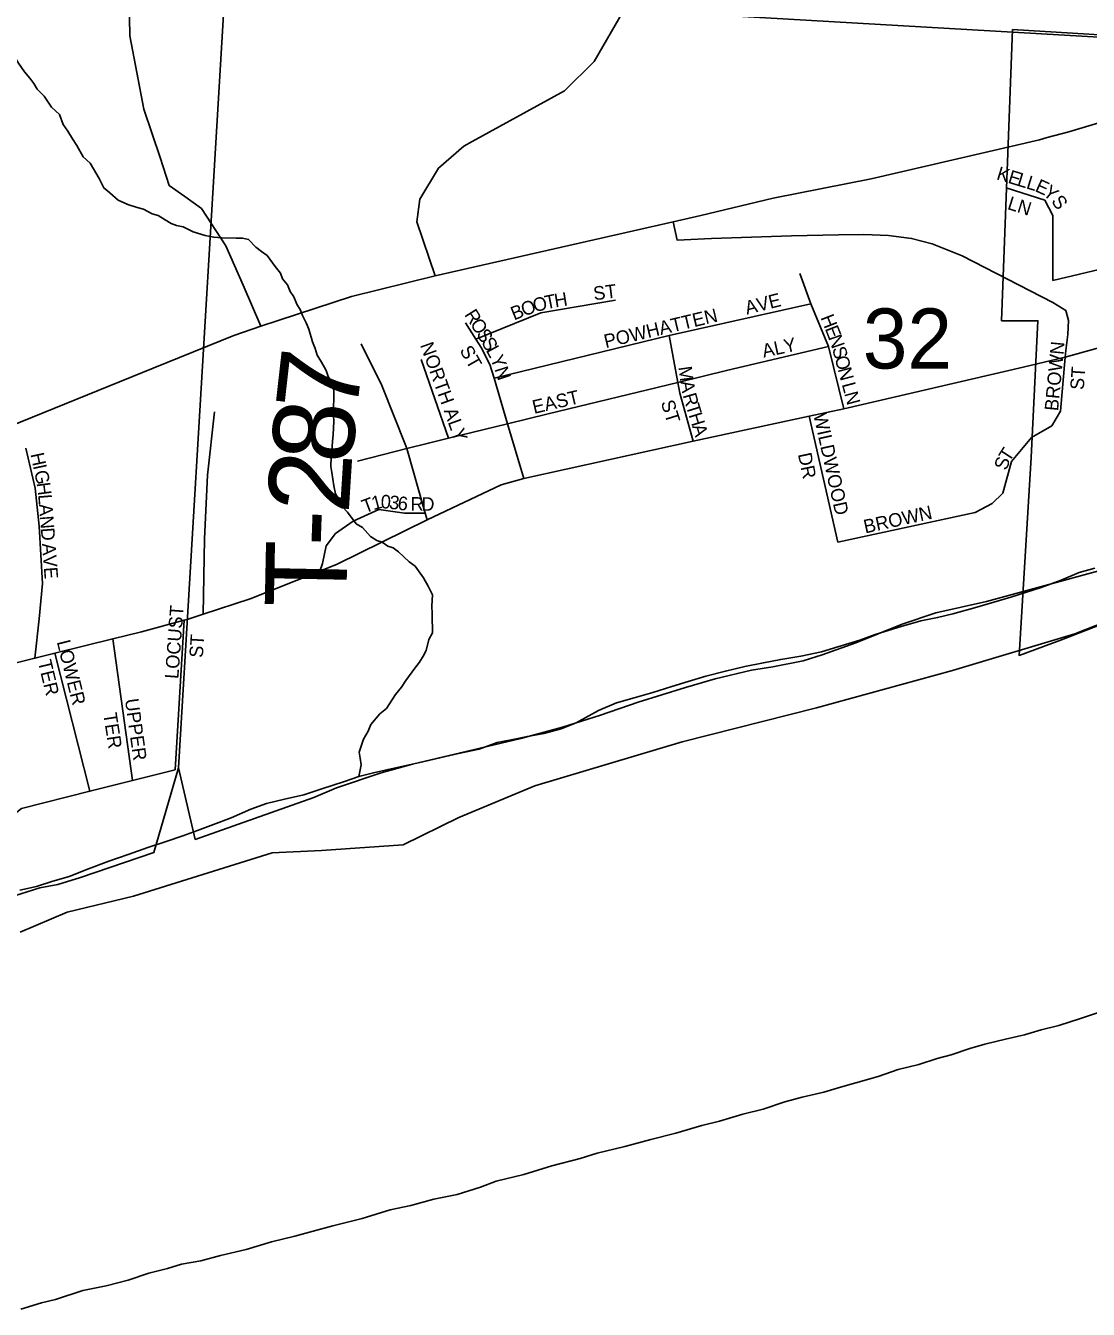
# Model space of a CAD drawing. Extents: x 0 to 34, y 0 to 22.
# Drawn here: x 3.368 to 4.109, y 15.164 to 16.058 of the extents above; entities that cross this region are included whole.
import ezdxf

# ---------------------------------------------------------------- set-up
doc = ezdxf.new("R2010")
doc.units = 0
for name, color, linetype in [('GM_X_City_Street', 7, 'Continuous'), ('GM_X_City_Street_Text', 7, 'Continuous'), ('GM_X_Corporation', 7, 'Continuous'), ('GM_X_County', 7, 'Continuous'), ('GM_X_County_Road', 7, 'Continuous'), ('GM_X_Interchange_Ramps', 7, 'Continuous'), ('GM_X_Major_River', 7, 'Continuous'), ('GM_X_Minor_River', 7, 'Continuous'), ('GM_X_Section', 7, 'Continuous'), ('GM_X_Section_Text', 7, 'Continuous'), ('GM_X_State_Route', 7, 'Continuous'), ('GM_X_Township', 7, 'Continuous'), ('GM_X_Township_Road', 7, 'Continuous'), ('GM_X_Township_Road_Text', 7, 'Continuous'), ('GM_X_Township_ROW', 7, 'Continuous'), ('GM_X_Township_Subdivision', 7, 'Continuous'), ('GM_X_Township_Subdivision_Text', 7, 'Continuous')]:
    doc.layers.add(name, color=color, linetype=linetype)

msp = doc.modelspace()

# ---------------------------------------------------------------- linework, layer by layer
at = {"layer": 'GM_X_City_Street'}
for points in [[(4.08456, 15.88074), (4.08464, 15.92599), (4.07896, 15.93664), (4.05197, 15.94531)], [(4.08456, 15.88074), (4.19618, 15.90713), (4.22201, 15.92)], [(4.09304, 15.82718), (4.1424, 15.84105), (4.16933, 15.84846), (4.26803, 15.87561), (4.3744, 15.90487), (4.44235, 15.92357)], [(4.06976, 15.77117), (4.08375, 15.77949), (4.08983, 15.78952), (4.09304, 15.82718)], [(4.0833, 15.82492), (4.09304, 15.82718)]]:
    msp.add_lwpolyline(points, dxfattribs=at)
at = {"layer": 'GM_X_Corporation'}
msp.add_lwpolyline([(4.14073, 15.64967), (4.09056, 15.63014), (4.06097, 15.61941), (4.06937, 15.75741), (4.07411, 15.85262), (4.04883, 15.85269), (4.05648, 16.05554), (4.29607, 16.04108)], dxfattribs=at)
at = {"layer": 'GM_X_County'}
msp.add_lwpolyline([(3.36466, 15.42637), (3.39726, 15.44049), (3.44353, 15.45159), (3.54023, 15.48177), (3.57475, 15.48336), (3.63165, 15.48727), (3.67032, 15.50633), (3.72339, 15.52846), (3.82616, 15.55905), (3.91983, 15.58279), (4.01463, 15.60881), (4.09995, 15.63443), (4.17199, 15.66269)], dxfattribs=at)
at = {"layer": 'GM_X_County_Road'}
for points in [[(3.65396, 15.88386), (3.64105, 15.9215), (3.64332, 15.93732), (3.65619, 15.959), (3.6738, 15.97433), (3.67979, 15.97757), (3.74411, 16.01283), (3.76477, 16.03339), (3.78552, 16.06911), (3.78668, 16.07724), (3.78765, 16.09175), (3.78406, 16.12231), (3.76062, 16.19637), (3.75023, 16.22244)], [(3.30564, 15.60024), (3.37488, 15.61744), (3.38872, 15.62088), (3.42928, 15.63096), (3.44921, 15.63591), (3.47881, 15.64392), (3.48179, 15.64473), (3.49225, 15.64816), (3.52496, 15.65889), (3.57339, 15.67813), (3.58555, 15.68296), (3.64839, 15.71388), (3.69988, 15.73832), (3.71568, 15.7427), (3.8337, 15.76866), (3.9146, 15.78602), (3.93887, 15.79127), (4.06381, 15.82038)], [(4.06381, 15.82038), (4.0833, 15.82492)]]:
    msp.add_lwpolyline(points, dxfattribs=at)
at = {"layer": 'GM_X_Interchange_Ramps'}
msp.add_lwpolyline([(3.8199, 15.92148), (3.82257, 15.90884), (3.84662, 15.90999), (3.90233, 15.91185), (3.93522, 15.91249), (3.95279, 15.91282), (3.96998, 15.912), (3.98609, 15.91003), (4.00039, 15.90624), (4.02127, 15.89786), (4.08457, 15.86531), (4.09365, 15.85971), (4.09542, 15.85281), (4.09509, 15.84295), (4.09361, 15.83193), (4.09304, 15.82718)], dxfattribs=at)
at = {"layer": 'GM_X_Major_River'}
for points in [[(4.11385, 15.68021), (4.10288, 15.67714), (4.09041, 15.67179), (4.07642, 15.66681), (4.06621, 15.66337), (4.05524, 15.65992), (4.04352, 15.65647), (4.0299, 15.65263), (4.01477, 15.64841), (4.00418, 15.64572), (3.99245, 15.64341), (3.97884, 15.63957), (3.96068, 15.63383), (3.9501, 15.63), (3.93459, 15.6254), (3.92325, 15.62195), (3.90887, 15.61887), (3.89487, 15.61655), (3.88276, 15.61424), (3.8699, 15.61154), (3.85629, 15.60847), (3.84267, 15.60501), (3.83019, 15.60118), (3.81884, 15.59773), (3.80561, 15.59352), (3.79275, 15.58968), (3.78027, 15.58623), (3.76779, 15.58088), (3.7523, 15.57248), (3.74171, 15.56828), (3.72961, 15.56483), (3.71826, 15.5629), (3.70691, 15.56059), (3.69707, 15.55866), (3.6846, 15.55407), (3.67022, 15.55099), (3.65812, 15.5483), (3.64525, 15.54523), (3.63164, 15.54215), (3.62104, 15.53984), (3.61083, 15.53754), (3.60062, 15.53485), (3.59079, 15.53141), (3.5749, 15.52643)], [(3.5749, 15.52643), (3.56243, 15.52222), (3.54881, 15.51914), (3.53633, 15.51607), (3.52536, 15.51224), (3.51175, 15.50613), (3.49927, 15.50154), (3.48831, 15.49734), (3.4781, 15.49351), (3.46637, 15.48969), (3.45352, 15.48547), (3.4399, 15.4805), (3.42629, 15.47591), (3.4123, 15.47056), (3.39869, 15.46521), (3.38659, 15.46176), (3.376, 15.45831), (3.36427, 15.45562)], [(3.36507, 15.16355), (3.37944, 15.16814), (3.38928, 15.17045), (3.40818, 15.17657), (3.42445, 15.18002), (3.43996, 15.18386), (3.45433, 15.18884), (3.46719, 15.19191), (3.47702, 15.19497), (3.49064, 15.19728), (3.50426, 15.20111), (3.52204, 15.20534), (3.53981, 15.2107), (3.55608, 15.21454), (3.56894, 15.21799), (3.58255, 15.22182), (3.60298, 15.22681), (3.62264, 15.23294), (3.63702, 15.23601), (3.6529, 15.24023), (3.66917, 15.24369), (3.68543, 15.24867), (3.6964, 15.25287), (3.71569, 15.25748), (3.73536, 15.26361), (3.75502, 15.2686), (3.76675, 15.27243), (3.78604, 15.27704), (3.80419, 15.28202), (3.82159, 15.28624), (3.83975, 15.29161), (3.85223, 15.29468), (3.86849, 15.29966), (3.88249, 15.30311), (3.89761, 15.30809), (3.90972, 15.31154), (3.92485, 15.315), (3.93657, 15.31845), (3.94716, 15.32152), (3.96267, 15.32573), (3.97666, 15.33071), (3.99104, 15.33417), (4.00389, 15.33838), (4.01373, 15.34106), (4.02658, 15.34527), (4.03718, 15.34834), (4.05155, 15.3518), (4.06479, 15.35487), (4.07651, 15.35832), (4.08861, 15.36139), (4.10374, 15.36637), (4.11774, 15.37097)]]:
    msp.add_lwpolyline(points, dxfattribs=at)
at = {"layer": 'GM_X_Minor_River'}
for points in [[(3.37418, 16.01798), (3.37122, 16.02183), (3.3675, 16.02608), (3.36345, 16.03223), (3.36013, 16.03761), (3.35569, 16.04377), (3.35197, 16.04764), (3.35551, 16.05519)], [(3.60062, 15.53485), (3.60223, 15.54308), (3.60155, 15.54766), (3.60087, 15.55185), (3.60406, 15.56091), (3.60719, 15.56656), (3.60916, 15.57109), (3.61535, 15.57859), (3.61996, 15.58231), (3.62619, 15.59209), (3.63045, 15.59734), (3.63356, 15.60185), (3.63977, 15.61049), (3.64288, 15.61461), (3.6456, 15.61875), (3.64757, 15.6229), (3.64959, 15.63047), (3.65194, 15.63499), (3.65201, 15.63879), (3.65172, 15.64373), (3.6518, 15.64867), (3.65151, 15.65362), (3.65203, 15.6616), (3.64911, 15.66773), (3.6458, 15.67348), (3.63988, 15.68157), (3.63577, 15.68468), (3.62832, 15.69164), (3.62458, 15.69437), (3.62081, 15.69557), (3.61707, 15.69829), (3.6133, 15.6995), (3.60881, 15.70223), (3.60323, 15.70841), (3.59874, 15.71115), (3.59282, 15.71923), (3.5891, 15.72309), (3.58728, 15.7273), (3.58433, 15.73192), (3.58329, 15.73764), (3.58193, 15.74678), (3.58125, 15.75098), (3.58137, 15.75782), (3.58183, 15.76199), (3.58231, 15.76845), (3.58278, 15.77338), (3.58332, 15.7825), (3.58301, 15.78669), (3.58332, 15.80417), (3.58189, 15.80913), (3.57932, 15.81374), (3.57788, 15.81795), (3.57457, 15.82371), (3.57163, 15.8287), (3.57019, 15.83328), (3.56838, 15.83788), (3.56588, 15.84667), (3.56407, 15.85126), (3.5615, 15.85624), (3.56005, 15.86007), (3.55748, 15.8643), (3.55529, 15.86928), (3.55271, 15.87312), (3.55089, 15.87772), (3.54756, 15.88196), (3.54611, 15.88578), (3.5424, 15.89041), (3.53686, 15.89811), (3.53274, 15.90084), (3.529, 15.90394), (3.5238, 15.90935), (3.51964, 15.91018), (3.5151, 15.91026), (3.50525, 15.91042), (3.49958, 15.9109), (3.49354, 15.91214), (3.48525, 15.91456), (3.47812, 15.91811), (3.47359, 15.91895), (3.46983, 15.92053), (3.4657, 15.92288), (3.46083, 15.926), (3.45669, 15.92721), (3.45068, 15.93036), (3.44616, 15.93157), (3.43975, 15.93358), (3.43299, 15.93674), (3.42702, 15.94178), (3.42291, 15.94527), (3.41962, 15.9518), (3.41337, 15.96255), (3.40852, 15.96681), (3.40411, 15.97487), (3.40116, 15.97949), (3.39785, 15.98487), (3.39452, 15.98949), (3.39199, 15.99638), (3.3864, 16.00141), (3.38122, 16.00911), (3.37639, 16.01413), (3.37418, 16.01798)]]:
    msp.add_lwpolyline(points, dxfattribs=at)
at = {"layer": 'GM_X_Section'}
msp.add_lwpolyline([(3.56848, 17.09992), (4.65367, 17.04009), (4.59377, 16.02271), (3.50743, 16.08595)], close=True, dxfattribs=at)
for points in [[(3.35178, 15.44893), (3.3783, 15.45728), (3.3908, 15.45956), (3.40671, 15.4645), (3.45785, 15.48197), (3.47486, 15.54109), (3.50743, 16.08595)], [(4.11661, 15.67833), (4.07911, 15.66807), (4.03819, 15.65705), (4.00296, 15.64907), (3.97948, 15.64109), (3.94728, 15.62819), (3.92379, 15.61984), (3.91054, 15.61566), (3.88932, 15.61148), (3.87454, 15.60919), (3.84916, 15.60311), (3.82833, 15.59704), (3.79537, 15.58678), (3.76923, 15.57767), (3.74272, 15.56932), (3.71354, 15.56134), (3.6715, 15.55146), (3.63816, 15.54347), (3.61619, 15.5374), (3.58513, 15.52714), (3.56922, 15.52031), (3.48664, 15.49108), (3.47486, 15.54109), (3.50743, 16.08595), (4.59377, 16.02271)]]:
    msp.add_lwpolyline(points, dxfattribs=at)
at = {"layer": 'GM_X_State_Route'}
for points in [[(4.08066, 15.98026), (4.09572, 15.98424), (4.11885, 15.99129), (4.14694, 16.00274), (4.16618, 16.01159), (4.18386, 16.02251), (4.21906, 16.04734), (4.22866, 16.05641)], [(3.83917, 15.92604), (3.88965, 15.93798), (3.95787, 15.95163), (4.07516, 15.9788), (4.08066, 15.98026)], [(2.61749, 15.58832), (2.70618, 15.61976), (2.72928, 15.62644), (2.76674, 15.6343), (2.78799, 15.63834), (2.95386, 15.66437), (3.00544, 15.67108), (3.06256, 15.68195), (3.10651, 15.69143), (3.1523, 15.70415), (3.21313, 15.72427), (3.34959, 15.77585), (3.45728, 15.81963), (3.51354, 15.84236), (3.53233, 15.84888), (3.59568, 15.86952), (3.65396, 15.88386), (3.8199, 15.92148), (3.83917, 15.92604)]]:
    msp.add_lwpolyline(points, dxfattribs=at)
at = {"layer": 'GM_X_Township'}
msp.add_lwpolyline([(3.36466, 15.42637), (3.39726, 15.44049), (3.44353, 15.45159), (3.54023, 15.48177), (3.57475, 15.48336), (3.63165, 15.48727), (3.67032, 15.50633), (3.72339, 15.52846), (3.82616, 15.55905), (3.91983, 15.58279), (4.01463, 15.60881), (4.09995, 15.63443), (4.17199, 15.66269)], dxfattribs=at)
at = {"layer": 'GM_X_Township_Road'}
for points in [[(3.53233, 15.84888), (3.52005, 15.87738), (3.50802, 15.90491), (3.49091, 15.93081), (3.47932, 15.93921)], [(3.64839, 15.71388), (3.64705, 15.71854), (3.63405, 15.76353), (3.63348, 15.7655), (3.6167, 15.80762), (3.60222, 15.83646)], [(3.49225, 15.64816), (3.49302, 15.70058), (3.49518, 15.74503), (3.5, 15.7891)]]:
    msp.add_lwpolyline(points, dxfattribs=at)
at = {"layer": 'GM_X_Township_ROW'}
msp.add_lwpolyline([(3.47932, 15.93921), (3.46855, 15.94703), (3.46208, 15.96645), (3.45083, 16.00022), (3.44108, 16.05118), (3.43998, 16.11516), (3.4389, 16.15202)], dxfattribs=at)
at = {"layer": 'GM_X_Township_Subdivision'}
for points in [[(3.93887, 15.79127), (3.92825, 15.83474), (3.91574, 15.86444), (3.90826, 15.88559)], [(3.68223, 15.83984), (3.72763, 15.85805), (3.77953, 15.86692)], [(3.91574, 15.86444), (3.81712, 15.84232), (3.69495, 15.81259)], [(3.71568, 15.7427), (3.70438, 15.78082), (3.69495, 15.81259), (3.69209, 15.82225), (3.686, 15.83401), (3.68223, 15.83984), (3.67496, 15.85108)], [(3.8337, 15.76866), (3.82443, 15.80207), (3.82305, 15.80964), (3.81712, 15.84232)], [(3.59985, 15.75475), (3.63405, 15.76353), (3.64919, 15.76741), (3.6632, 15.77082), (3.70438, 15.78082), (3.73269, 15.78769), (3.82305, 15.80964), (3.85792, 15.81811), (3.92825, 15.83474)], [(3.6632, 15.77082), (3.64412, 15.82566)], [(3.9146, 15.78602), (3.93461, 15.69828)], [(3.93461, 15.69828), (4.03046, 15.71904), (4.0422, 15.72514), (4.04976, 15.73238), (4.05577, 15.75442), (4.06976, 15.77117)], [(3.37488, 15.61744), (3.37793, 15.64485), (3.38014, 15.66954), (3.37777, 15.70941), (3.37505, 15.73599), (3.36853, 15.76371)], [(3.57339, 15.67813), (3.57531, 15.68332), (3.57793, 15.69586), (3.58436, 15.70423), (3.59685, 15.713), (3.61464, 15.72102), (3.63247, 15.7184), (3.64705, 15.71854)], [(3.47275, 15.53966), (3.47881, 15.64392)], [(3.44281, 15.53215), (3.42928, 15.63096)], [(3.41316, 15.5247), (3.38872, 15.62088)], [(3.25065, 15.52251), (3.26653, 15.47833), (3.31344, 15.48757), (3.33523, 15.49259), (3.35701, 15.506), (3.3654, 15.51272), (3.41316, 15.5247), (3.44281, 15.53215), (3.47275, 15.53966)]]:
    msp.add_lwpolyline(points, dxfattribs=at)

# ---------------------------------------------------------------- texts
at = {"layer": 'GM_X_City_Street_Text'}
for s, rotation, p in [('K', 343.07146, (4.0447, 15.95133)), ('E', 343.07146, (4.05268, 15.94891)), ('L', 343.07146, (4.05905, 15.94697)), ('L', 343.07146, (4.06543, 15.94502)), ('E', 335.60966, (4.07151, 15.9432)), ('Y', 320.68605, (4.07703, 15.94079)), ('LN', 342.47519, (4.05231, 15.9306)), ('S', 305.76244, (4.08303, 15.93598)), ('BROWN', 84.60953, (4.08818, 15.78944)), ('ST', 86.42562, (4.10611, 15.8042))]:
    msp.add_text(s, height=0.00947, rotation=rotation, dxfattribs=at).set_placement(p)
at = {"layer": 'GM_X_Section_Text'}
msp.add_text('32', height=0.041856, rotation=0.00001, dxfattribs=at).set_placement((3.95204, 15.81933))
at = {"layer": 'GM_X_Township_Road_Text'}
for s, rotation, p in [('7', 83.5491, (3.59901, 15.78663)), ('8', 84.58504, (3.59573, 15.75206)), ('2', 86.38606, (3.59356, 15.7176)), ('-', 87.95439, (3.59275, 15.69469)), ('T', 88.83422, (3.59189, 15.65243))]:
    msp.add_text(s, height=0.05682, rotation=rotation, dxfattribs=at).set_placement(p)
at = {"layer": 'GM_X_Township_Subdivision_Text'}
for s, rotation, p in [('ST', 7.12586, (3.76474, 15.86687)), ('O', 20.05372, (3.71579, 15.85559)), ('O', 15.66862, (3.72343, 15.85839)), ('T', 11.28353, (3.73127, 15.86059)), ('H', 9.09098, (3.73772, 15.86188)), ('AVE', 14.03441, (3.87119, 15.85683)), ('R', 302.22647, (3.67396, 15.85689)), ('B', 22.24627, (3.70894, 15.85278)), ('POWHATTEN', 13.39189, (3.77285, 15.8335)), ('H', 291.29359, (3.92245, 15.85492)), ('O', 302.20392, (3.67796, 15.85055)), ('S', 300.93623, (3.68237, 15.84354)), ('E', 291.27756, (3.92547, 15.84716)), ('NORTH ALY', 289.79916, (3.6433, 15.83571)), ('S', 299.51274, (3.68577, 15.83788)), ('ALY', 12.09442, (3.88292, 15.82685)), ('N', 289.22075, (3.92786, 15.84103)), ('ST', 299.74279, (3.67069, 15.83207)), ('L', 298.60447, (3.68903, 15.83211)), ('Y', 292.04697, (3.6921, 15.82652)), ('S', 285.57201, (3.93056, 15.83331)), ('N', 288.36756, (3.69518, 15.81895)), ('M', 277.93, (3.82339, 15.82034)), ('O', 285.05743, (3.93234, 15.82691)), ('N', 285.07819, (3.93451, 15.81886)), ('EAST', 13.24059, (3.72288, 15.78767)), ('A', 279.41072, (3.82481, 15.81017)), ('R', 286.03801, (3.82644, 15.80078)), ('L', 285.06254, (3.93733, 15.8084)), ('N', 285.05743, (3.93906, 15.80197)), ('ST', 287.35773, (3.81111, 15.79578)), ('T', 287.10407, (3.82857, 15.79339)), ('H', 287.10435, (3.83053, 15.78702)), ('WILDWOOD', 282.45148, (3.91753, 15.78715)), ('A', 287.10435, (3.83298, 15.77905)), ('H', 282.02149, (3.3717, 15.75965)), ('DR', 281.8933, (3.90676, 15.75965)), ('S', 71.91496, (4.05235, 15.74787)), ('T', 57.20126, (4.05414, 15.75362)), ('I', 282.02093, (3.37344, 15.7515)), ('G', 281.99926, (3.3743, 15.74742)), ('H', 277.54031, (3.376, 15.73946)), ('L', 274.6495, (3.37708, 15.73133)), ('1', 14.73095, (3.61091, 15.72056)), ('0', 357.13643, (3.61579, 15.72197)), ('3', 353.01637, (3.62144, 15.72169)), ('6', 354.22066, (3.62744, 15.72096)), ('A', 274.44135, (3.37762, 15.72469)), ('T', 20.51127, (3.60491, 15.7183)), ('R', 359.8095, (3.63675, 15.72022)), ('D', 359.99551, (3.64429, 15.72019)), ('BROWN', 12.40751, (3.95374, 15.70434)), ('N', 274.47032, (3.37827, 15.71638)), ('D', 274.46325, (3.37892, 15.70807)), ('A', 274.46783, (3.37976, 15.69727)), ('V', 274.44135, (3.38041, 15.68896)), ('E', 274.48596, (3.38105, 15.68064)), ('LOCUST', 85.7619, (3.47484, 15.60274)), ('ST', 86.41202, (3.49194, 15.61753)), ('LOWER', 284.03739, (3.39002, 15.62887)), ('TER', 283.49694, (3.37685, 15.61509)), ('UPPER', 277.94416, (3.43756, 15.58868)), ('TER', 278.74964, (3.42246, 15.57876))]:
    msp.add_text(s, height=0.00947, rotation=rotation, dxfattribs=at).set_placement(p)

doc.saveas('drawing.dxf')
